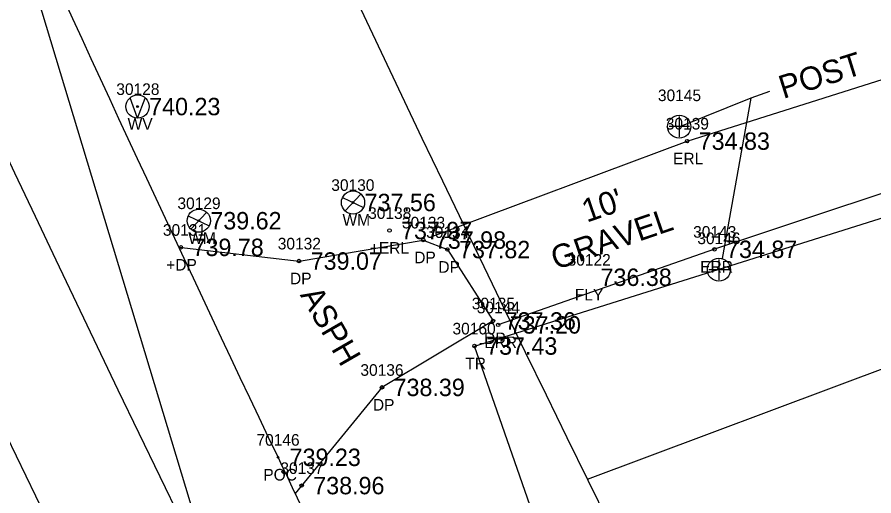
# Model space of a CAD drawing. Extents: x 1375131 to 1378678, y 999028 to 1004053.
# Drawn here: x 1376873.2 to 1376947, y 1002476.7 to 1002518 of the extents above; entities that cross this region are included whole.
import ezdxf

# ---------------------------------------------------------------- set-up
doc = ezdxf.new("R2010")
doc.units = 0
for name, color, linetype in [('Default', 7, 'Continuous'), ('RD_EX_BldgApp', 7, 'Continuous'), ('RD_EX_Driveway', 7, 'Continuous'), ('RD_EX_Driveway_txCode', 7, 'Continuous'), ('RD_EX_DV_Prop', 7, 'Continuous'), ('RD_EX_Fence_Other_txCode', 7, 'Continuous'), ('RD_EX_Road', 7, 'Continuous'), ('RD_EX_Road_txCode', 7, 'Continuous'), ('RD_EX_RW', 7, 'Continuous'), ('RD_EX_SU_Elec', 7, 'Continuous'), ('RD_EX_TX_Driveway_ELEV', 7, 'Continuous'), ('RD_EX_TX_Fence_Other_ELEV', 7, 'Continuous'), ('RD_EX_TX_Road_ELEV', 7, 'Continuous'), ('RD_EX_TX_UT_ELEV', 7, 'Continuous'), ('RD_EX_TX_VEG_ELEV', 7, 'Continuous'), ('RD_EX_UT', 7, 'Continuous'), ('RD_EX_UT_txCode', 7, 'Continuous'), ('RD_EX_VEG', 7, 'Continuous'), ('RD_EX_VEG_txCode', 7, 'Continuous'), ('RD_HC_Cl', 7, 'Continuous'), ('RD_SMD_Locator', 7, 'Continuous'), ('RD_TX_Misc1', 7, 'Continuous'), ('RD_TX_Misc2', 7, 'Continuous')]:
    doc.layers.add(name, color=color, linetype=linetype)

msp = doc.modelspace()

# ---------------------------------------------------------------- linework, layer by layer
at = {"layer": 'Default'}
for p, q in [((1376930.211, 1002509.395), (1376930.211, 1002507.645)), ((1376931.086, 1002508.52), (1376929.336, 1002508.52)), ((1376933.63, 1002497.073), (1376933.63, 1002495.323)), ((1376934.505, 1002496.198), (1376932.755, 1002496.198))]:
    msp.add_line(p, q, dxfattribs=at)
at = {"layer": 'RD_EX_BldgApp'}
for centre in [(1376930.211, 1002508.52), (1376933.63, 1002496.198)]:
    msp.add_circle(centre, 0.996, dxfattribs=at)
at = {"layer": 'RD_EX_Driveway'}
msp.add_lwpolyline([(1376887.099, 1002498.141), (1376897.457, 1002496.942), (1376908.161, 1002498.751), (1376910.24, 1002497.931), (1376914.176, 1002491.781), (1376904.6, 1002486.054), (1376897.123, 1002476.909)], dxfattribs=at)
at = {"layer": 'RD_EX_DV_Prop'}
msp.add_line((1376922.303, 1002478.143), (1377313.16, 1002624.462), dxfattribs=at)
at = {"layer": 'RD_EX_Road'}
for points in [[(1376908.742, 1002499.002), (1376930.889, 1002507.274), (1376984.297, 1002524.174)], [(1376987.029, 1002515.581), (1376956.453, 1002505.691), (1376933.246, 1002497.953), (1376914.607, 1002491.438)]]:
    msp.add_lwpolyline(points, dxfattribs=at)
for points in [[(1377013.314, 1002264.907), (1376982.808, 1002315.683), (1376952.468, 1002370.341), (1376923.174, 1002424.32), (1376895.644, 1002480.03), (1376870.11, 1002535.049), (1376846.329, 1002588.864), (1376822.292, 1002645.031), (1376786.564, 1002736.458)], [(1376994.747, 1002253.913), (1376964.909, 1002306.463), (1376934.396, 1002359.987), (1376904.773, 1002415.485), (1376877.271, 1002471.511), (1376851.037, 1002526.893), (1376827.48, 1002581.62), (1376804.191, 1002637.821), (1376768.457, 1002728.838)]]:
    msp.add_spline(points, degree=3, dxfattribs=at)
at = {"layer": 'RD_EX_RW'}
for radius in [2767, 2833]:
    msp.add_arc((1379404.86, 1003700.108), radius, 200.269954, 211.131166, dxfattribs=at)
at = {"layer": 'RD_EX_SU_Elec'}
msp.add_line((1376829.238, 1002670.592), (1376932.6, 1002329.066), dxfattribs=at)
at = {"layer": 'RD_EX_UT'}
for p, q in [((1376883.546, 1002509.257), (1376882.894, 1002510.998)), ((1376883.546, 1002509.257), (1376884.207, 1002510.979)), ((1376901.191, 1002502.405), (1376903.007, 1002501.548)), ((1376901.432, 1002501.257), (1376902.766, 1002502.705)), ((1376887.897, 1002500.836), (1376889.713, 1002499.979)), ((1376888.138, 1002499.688), (1376889.472, 1002501.136))]:
    msp.add_line(p, q, dxfattribs=at)
for centre in [(1376883.546, 1002510.253), (1376902.108, 1002501.986), (1376888.814, 1002500.417)]:
    msp.add_circle(centre, 1, dxfattribs=at)
at = {"layer": 'RD_EX_VEG'}
msp.add_lwpolyline([(1377016.163, 1002440.332), (1376948.43, 1002386.71), (1376912.576, 1002489.618), (1376961.851, 1002505.127), (1376995.25, 1002514.983)], dxfattribs=at)
at = {"layer": 'RD_HC_Cl'}
msp.add_arc((1379404.86, 1003700.108), 2800, 200.269954, 211.131166, dxfattribs=at)
at = {"layer": 'RD_SMD_Locator'}
for centre, radius in [((1376883.546, 1002510.253), 0.075), ((1376930.889, 1002507.274), 0.15), ((1376902.108, 1002501.986), 0.075), ((1376888.814, 1002500.417), 0.075), ((1376905.245, 1002499.57), 0.15), ((1376908.161, 1002498.751), 0.15), ((1376887.279, 1002498.12), 0.15), ((1376910.24, 1002497.931), 0.15), ((1376933.246, 1002497.953), 0.15), ((1376897.457, 1002496.942), 0.15), ((1376914.176, 1002491.781), 0.15), ((1376914.607, 1002491.438), 0.15), ((1376912.576, 1002489.618), 0.15), ((1376904.6, 1002486.054), 0.15), ((1376895.644, 1002480.03), 0.075), ((1376897.682, 1002477.593), 0.15)]:
    msp.add_circle(centre, radius, dxfattribs=at)
at = {"layer": 'RD_TX_Misc1'}
msp.add_line((1376936.375, 1002510.97), (1376933.926, 1002497.149), dxfattribs=at)
msp.add_lwpolyline([(1376937.979, 1002511.549), (1376936.375, 1002510.97), (1376930.323, 1002508.52)], dxfattribs=at)

# ---------------------------------------------------------------- texts
at = {"layer": 'Default'}
for s, p in [('30145', (1376928.376, 1002510.72)), ('30146', (1376931.772, 1002498.398))]:
    msp.add_text(s, height=1, dxfattribs=at).set_placement(p)
at = {"layer": 'RD_EX_Driveway_txCode'}
for s, p in [('30133', (1376906.326, 1002499.751)), ('30131', (1376885.728, 1002499.12)), ('30134', (1376908.405, 1002498.931)), ('30132', (1376895.622, 1002497.942)), ('+DP', (1376886.011, 1002496.12)), ('DP', (1376907.381, 1002496.751)), ('DP', (1376909.46, 1002495.931)), ('DP', (1376896.677, 1002494.942)), ('30135', (1376912.341, 1002492.781)), ('DP', (1376913.396, 1002489.781)), ('30136', (1376902.742, 1002487.054)), ('DP', (1376903.82, 1002484.054)), ('30137', (1376895.847, 1002478.593))]:
    msp.add_text(s, height=1, dxfattribs=at).set_placement(p)
at = {"layer": 'RD_EX_Fence_Other_txCode'}
for s, p in [('30122', (1376920.597, 1002496.544)), ('FLY', (1376921.219, 1002493.544))]:
    msp.add_text(s, height=1, dxfattribs=at).set_placement(p)
at = {"layer": 'RD_EX_Road_txCode'}
for s, p in [('30139', (1376929.054, 1002508.274)), ('ERL', (1376929.684, 1002505.274)), ('30138', (1376903.41, 1002500.57)), ('30143', (1376931.411, 1002498.953)), ('+ERL', (1376903.552, 1002497.57)), ('ERR', (1376932.018, 1002495.953)), ('30144', (1376912.772, 1002492.438)), ('-ERR', (1376912.969, 1002489.438)), ('70146', (1376893.786, 1002481.03)), ('POC', (1376894.376, 1002478.03))]:
    msp.add_text(s, height=1, dxfattribs=at).set_placement(p)
at = {"layer": 'RD_EX_TX_Driveway_ELEV'}
for s, p in [('737.98', (1376909.161, 1002498.001)), ('739.78', (1376888.279, 1002497.37)), ('737.82', (1376911.24, 1002497.181)), ('739.07', (1376898.457, 1002496.192)), ('737.36', (1376915.176, 1002491.031)), ('738.39', (1376905.6, 1002485.304)), ('738.96', (1376898.682, 1002476.843))]:
    msp.add_text(s, height=1.5, dxfattribs=at).set_placement(p)
at = {"layer": 'RD_EX_TX_Fence_Other_ELEV'}
msp.add_text('736.38', height=1.5, dxfattribs=at).set_placement((1376923.432, 1002494.794))
at = {"layer": 'RD_EX_TX_Road_ELEV'}
for s, p in [('734.83', (1376931.889, 1002506.524)), ('737.97', (1376906.245, 1002498.82)), ('734.87', (1376934.246, 1002497.203)), ('737.20', (1376915.607, 1002490.688)), ('739.23', (1376896.644, 1002479.28))]:
    msp.add_text(s, height=1.5, dxfattribs=at).set_placement(p)
at = {"layer": 'RD_EX_TX_UT_ELEV'}
for s, p in [('740.23', (1376884.546, 1002509.503)), ('737.56', (1376903.108, 1002501.236)), ('739.62', (1376889.814, 1002499.667))]:
    msp.add_text(s, height=1.5, dxfattribs=at).set_placement(p)
at = {"layer": 'RD_EX_TX_VEG_ELEV'}
msp.add_text('737.43', height=1.5, dxfattribs=at).set_placement((1376913.576, 1002488.868))
at = {"layer": 'RD_EX_UT_txCode'}
for s, p in [('30128', (1376881.711, 1002511.253)), ('WV', (1376882.688, 1002508.253)), ('30130', (1376900.234, 1002502.986)), ('30129', (1376886.979, 1002501.417)), ('WM', (1376901.202, 1002499.986)), ('WM', (1376887.908, 1002498.417))]:
    msp.add_text(s, height=1, dxfattribs=at).set_placement(p)
at = {"layer": 'RD_EX_VEG_txCode'}
for s, p in [('30160', (1376910.678, 1002490.618)), ('TR', (1376911.781, 1002487.618))]:
    msp.add_text(s, height=1, dxfattribs=at).set_placement(p)
at = {"layer": 'RD_TX_Misc1'}
msp.add_text('POST', height=2, rotation=17.47262, dxfattribs=at).set_placement((1376939.175, 1002510.903))
at = {"layer": 'RD_TX_Misc2'}
for s, rotation, p in [("10'", 18.89822, (1376922.245, 1002500.243)), ('GRAVEL', 18.89822, (1376919.582, 1002496.16)), ('ASPH', 300.0183, (1376897.505, 1002494.021))]:
    msp.add_text(s, height=2, rotation=rotation, dxfattribs=at).set_placement(p)

doc.saveas('drawing.dxf')
